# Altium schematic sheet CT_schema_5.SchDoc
size 287 x 160 mm
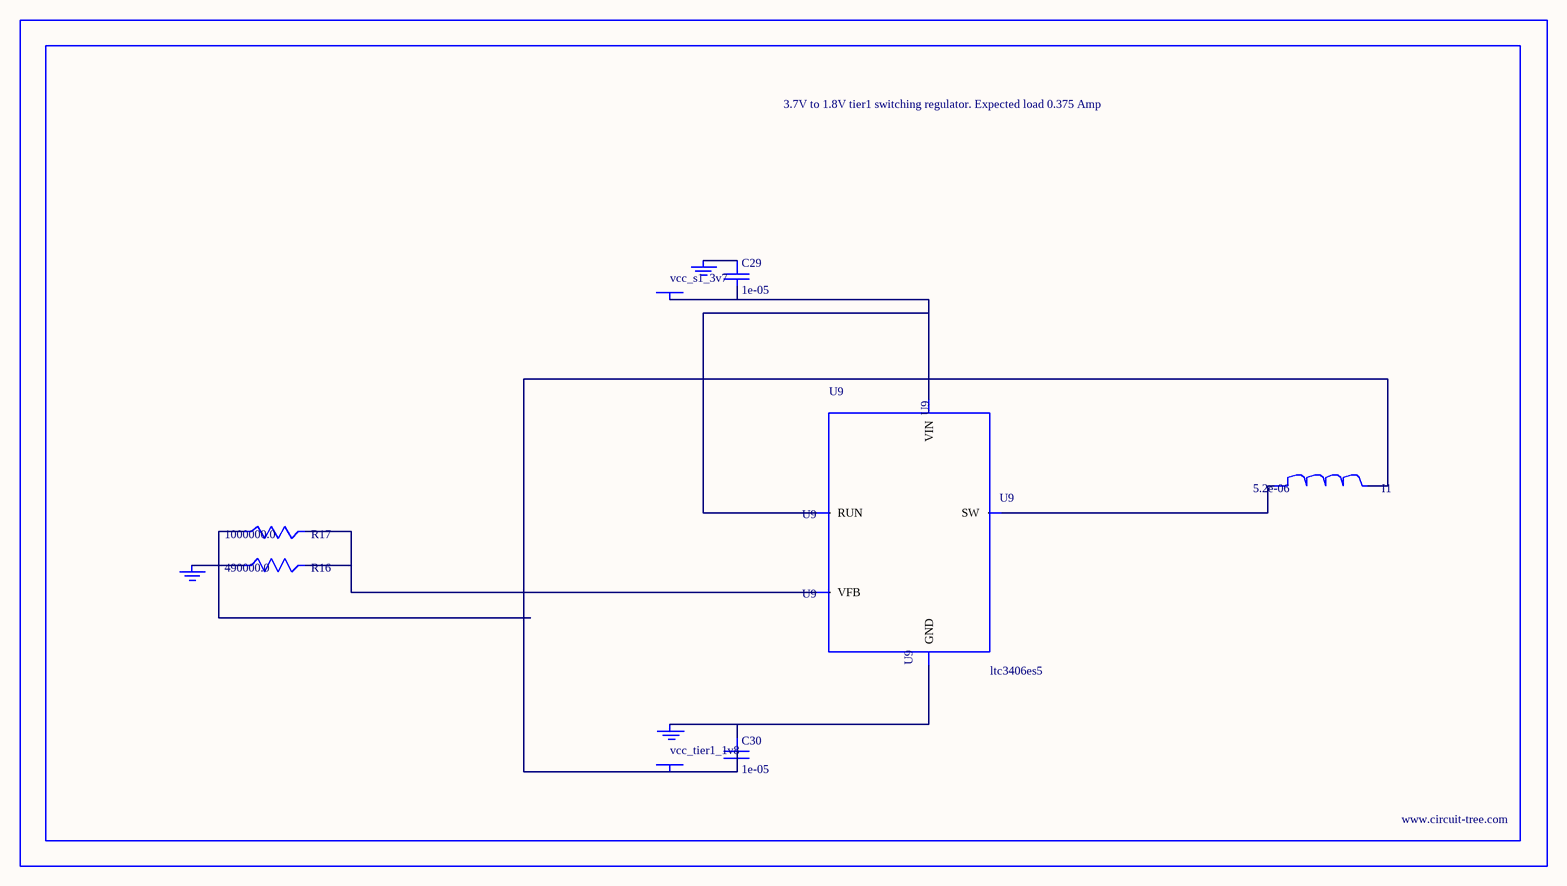
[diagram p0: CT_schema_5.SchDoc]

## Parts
BORDER4  (no value)
C29  1e-05  [C0805]
C30  1e-05  [C0805]
GND_INSTANCE_4_0  (no value)
GND_INSTANCE_4_1  (no value)
GND_INSTANCE_4_2  (no value)
I1  5.2e-06  [DR1040]
POWER_INSTANCE_4_0  vcc_tier1_1v8
POWER_INSTANCE_4_1  vcc_s1_3v7
R16  490000.0  [R0603]
R17  1000000.0  [R0603]
U9  ltc3406es5  [TSOT-23-5]

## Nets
NetC29_1: C29.1 GND_INSTANCE_4_1.0(GND)
NetC29_2: C29.2 POWER_INSTANCE_4_1.0(PWR) U9.1(RUN) U9.4(VIN)
NetC30_1: C30.1 GND_INSTANCE_4_0.0(GND) U9.2(GND)
NetC30_2: C30.2 I1.2 POWER_INSTANCE_4_0.0(PWR) R17.1
NetGND_INSTANCE_4_2_0: GND_INSTANCE_4_2.0(GND) R16.1
NetI1_1: I1.1 U9.3(SW)
NetR16_2: R16.2 R17.2 U9.5(VFB)

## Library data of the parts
BORDER4 = BORDER_PAGE4
C29 C30 = C0805C106K8RACTU
GND_INSTANCE_4_0-GND_INSTANCE_4_2 = GND
I1 = DR1040-5R2-R
POWER_INSTANCE_4_0 POWER_INSTANCE_4_1 = PWR
R16 = R16
R17 = RC0603JR-071ML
